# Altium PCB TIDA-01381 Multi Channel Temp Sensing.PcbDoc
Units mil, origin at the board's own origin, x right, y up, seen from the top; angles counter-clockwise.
Board outline 3285 x 2450 mil, 2 copper layers (Top Layer, Bottom Layer), stack 62 mil thick; 83 components, 41 nets, 183 pads, 135 vias.
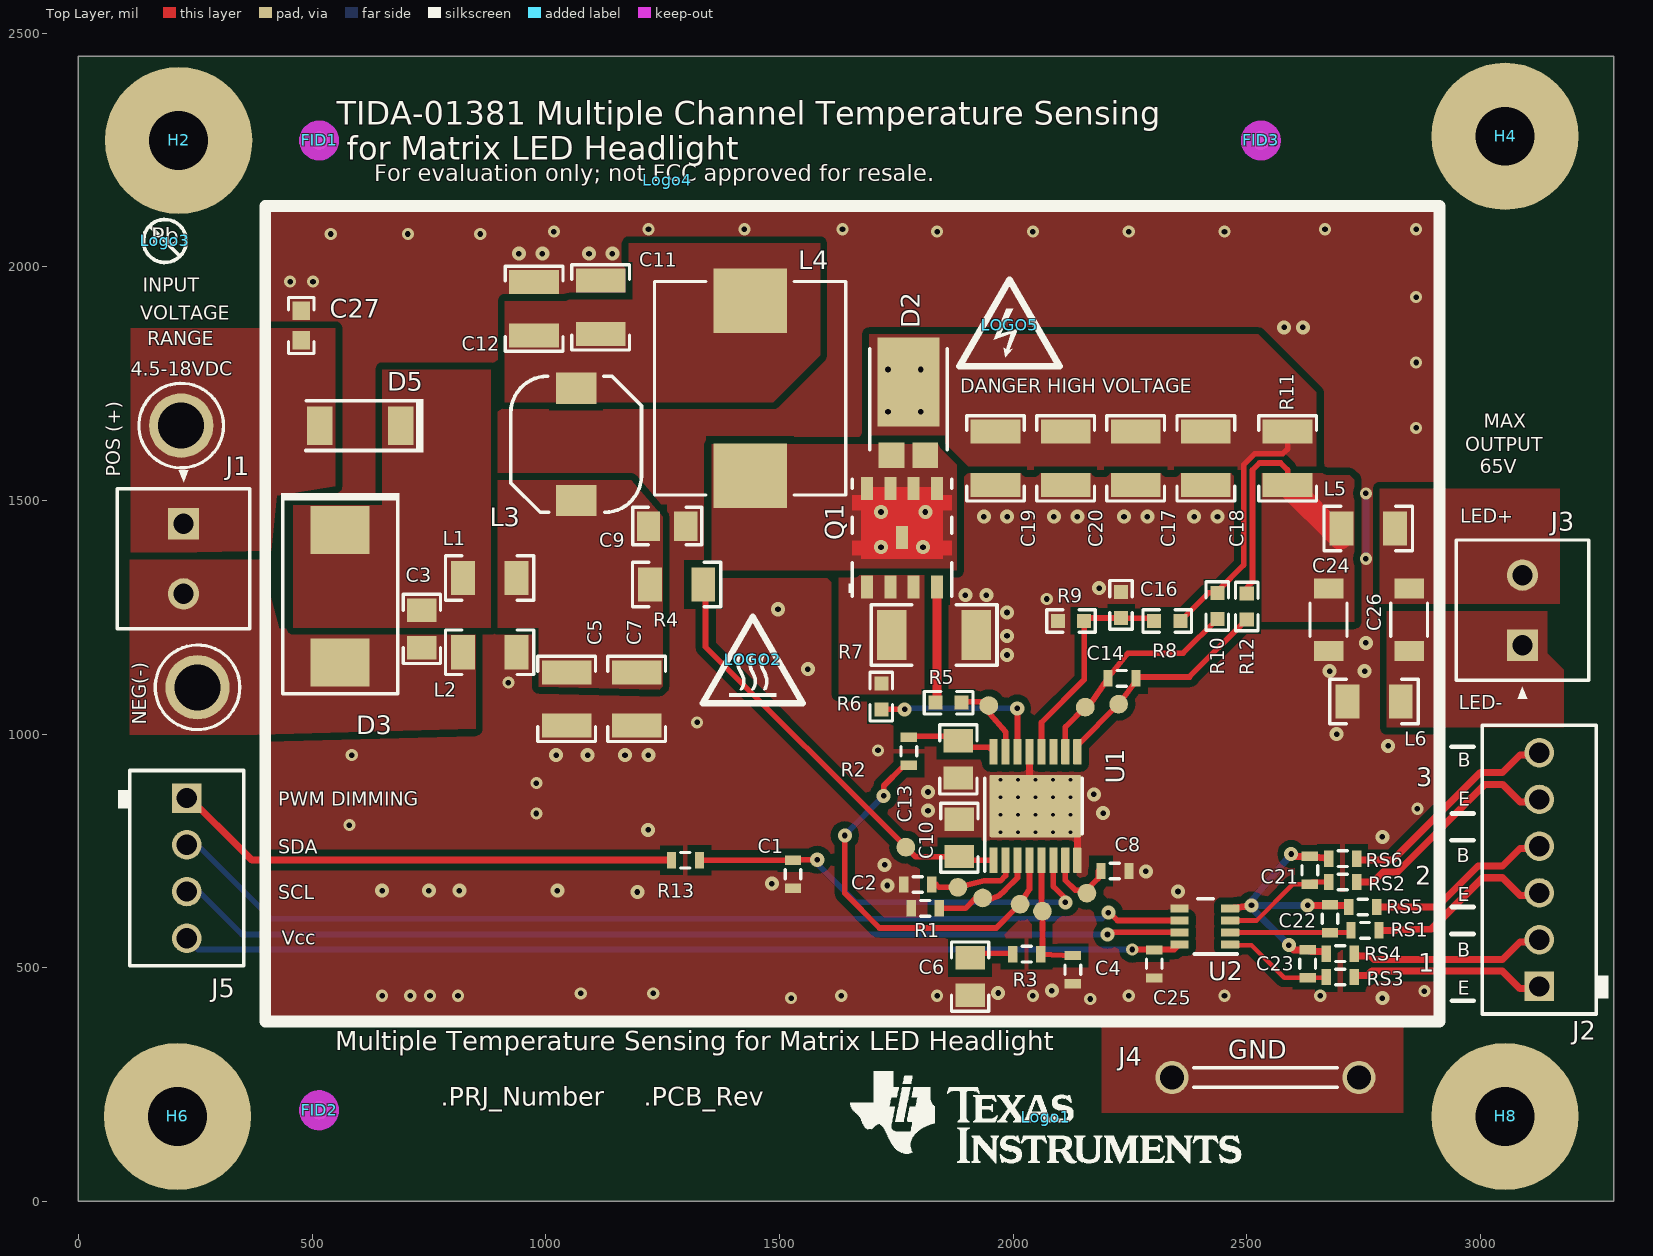
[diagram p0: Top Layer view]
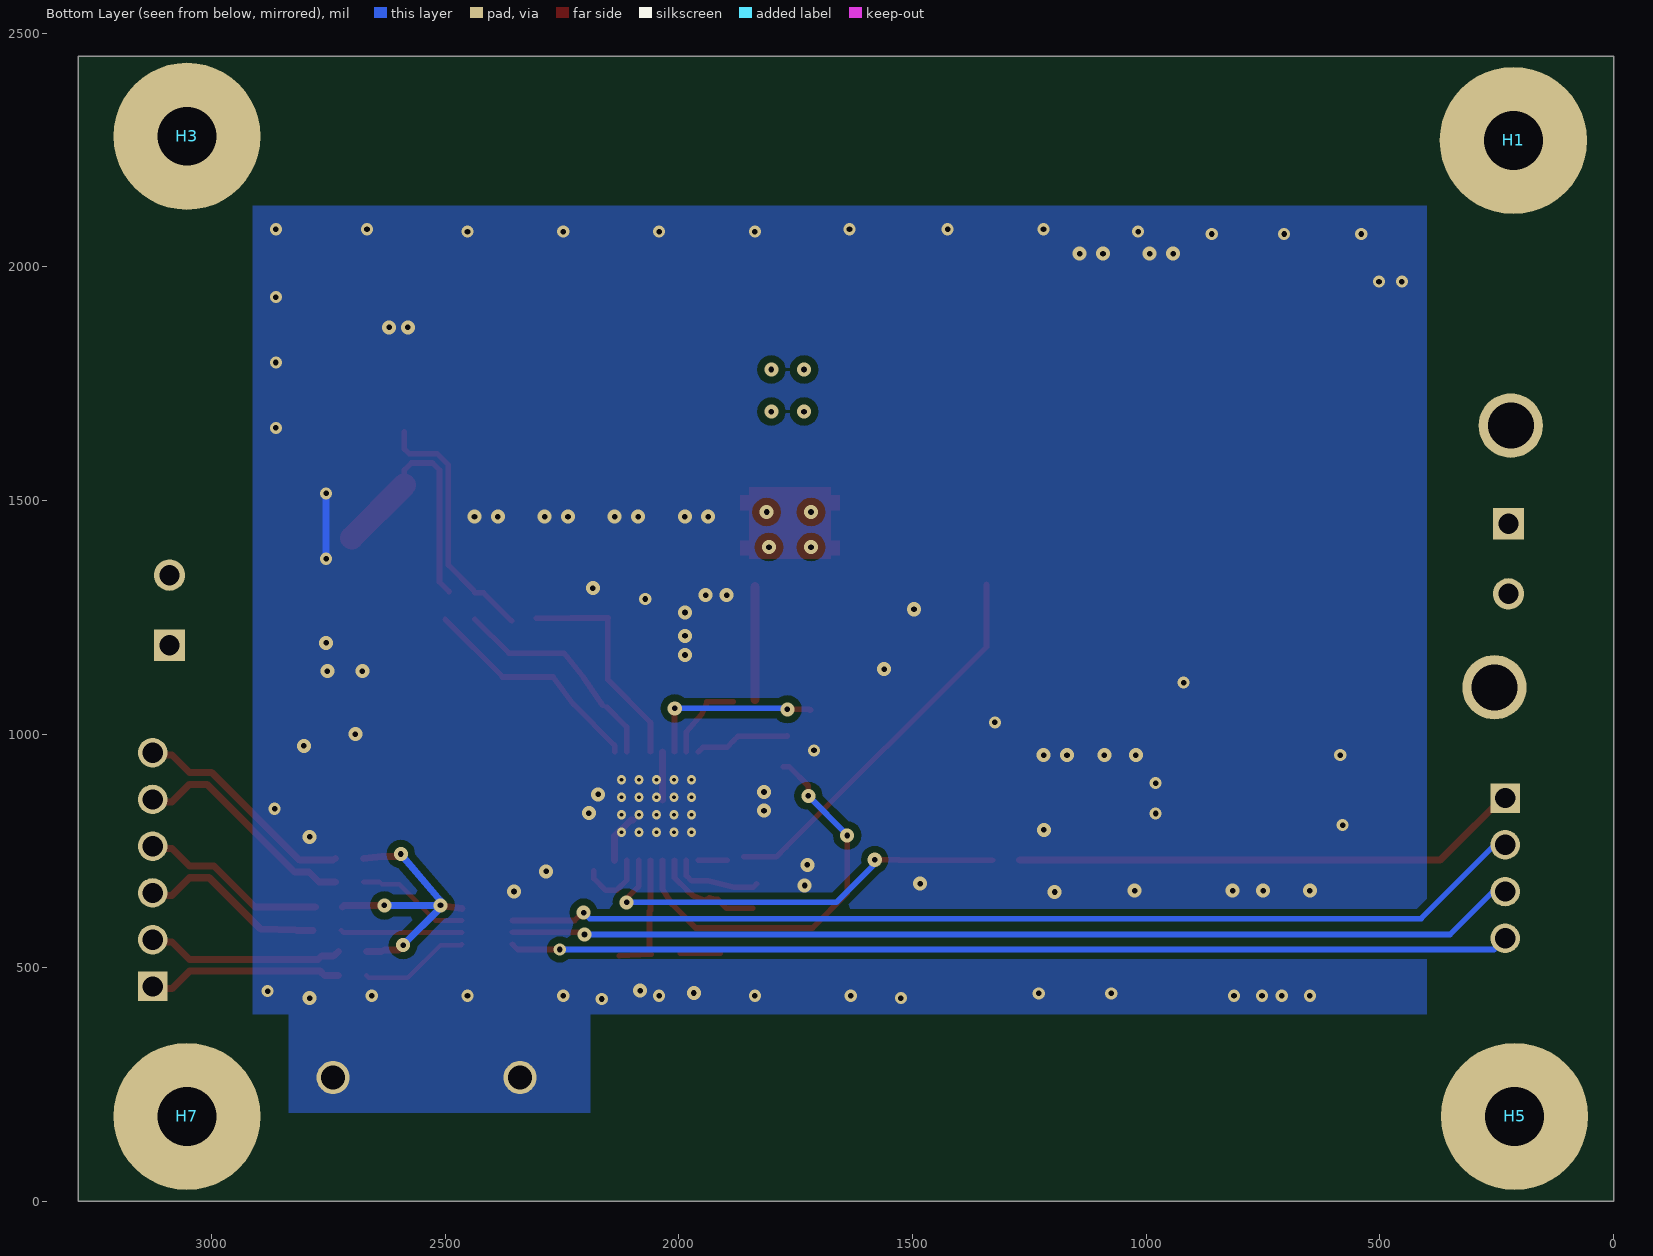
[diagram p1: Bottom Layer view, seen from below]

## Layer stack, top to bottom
Top Solder: solder mask 0.4, Solder Resist, Dk 3.5
Top Layer: signal copper 1.4
Dielectric1: core 59.2, FR-4, Dk 4.8
Bottom Layer: signal copper 1.4
Bottom Solder: solder mask 0.4, Solder Resist, Dk 3.5

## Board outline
0,0 3285,0 3285,2450 0,2450
cut-out: -1242,-1684 -1232,-1684 -1232,-1674 -1242,-1674

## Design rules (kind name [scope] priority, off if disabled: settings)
AcuteAngle [All] p1: minimum=4.50000000000000E+0001 checktracksonly=FALSE
AssemblyTestPointUsage [All] p1 off: valid=2
AssemblyTestpoint [All] p1 off: testpointundercomponent=TRUE minsize=40 maxsize=100 preferedsize=60 minholesize=0 maxholesize=40 preferedholesize=32 testpointgrid=1 usegrid=TRUE gridtolerance=0.01 allowsidetop=TRUE allowsidebottom=TRUE
Clearance Clearance_BoardEdge_Poly [OnCopper and InPoly vs IsKeepOut] p1: gap=25
Clearance Clearance_BoardEdge [OnCopper and Not InComponentClass('Logo') and not InComponentClass('FiducialMark') and not InRegion(1000,500,4000,800) and Not IsKeepout vs IsKeepOut] p2: gap=25
Clearance Clearance_Poly [InPolygon] p3: gap=15
Clearance [All] p4: gap=7
ComponentClearance ComponentClearance_MountingHoles [InComponent('H1') or InComponent('H2')or InComponent('H4') or InComponent('H5') or InComponent('H8')] p1: gap=0 collisioncheckmode=3 verticalgap=0 showdistances=FALSE
ComponentClearance ComponentClearance_Logo [InComponentClass('Logo')] p2: gap=0 collisioncheckmode=3 verticalgap=0 showdistances=FALSE
ComponentClearance ComponentClearance_SmallPassives [HasFootprint('0201*') or HasFootprint('0402*') or HasFootprint('0508') or HasFootprint('0603*') or HasFootprint('0612') or HasFootprint('0805*') or HasFootprint('0815*') or HasFootprint('0830*') or HasFootprint('1206*') or HasFootprint('1210*') or HasFootprint('1808*') or HasFootprint('1812*') or HasFootprint('1825*') or HasFootprint('2010*') or HasFootprint('2220*') or HasFootprint('2225*') or HasFootprint('2512*') or HasFootprint('2728*') or HasFootprint('3518*') vs HasFootprint('0201*') or HasFootprint('0402*') or HasFootprint('0508') or HasFootprint('0603*') or HasFootprint('0612') or HasFootprint('0805*') or HasFootprint('0815*') or HasFootprint('0830*') or HasFootprint('1206*') or HasFootprint('1210*') or HasFootprint('1808*') or HasFootprint('1812*') or HasFootprint('1825*') or HasFootprint('2010*') or HasFootprint('2220*') or HasFootprint('2225*') or HasFootprint('2512*') or HasFootprint('2728*') or HasFootprint('3518*')] p3: gap=10 collisioncheckmode=3 verticalgap=10 showdistances=FALSE
ComponentClearance [All] p4: gap=15 collisioncheckmode=3 verticalgap=30 showdistances=FALSE
DiffPairsRouting [All] p1: maxlimit=100 minlimit=10 mostfreqgap=10 toplayer_minwidth=15 toplayer_maxwidth=15 toplayer_prefwidth=15 bottomlayer_minwidth=15 bottomlayer_maxwidth=15 bottomlayer_prefwidth=15 maxuncoupledlength=1000
FabricationTestPointUsage TestPointUsage [All] p1 off: valid=2 allowmultiple=FALSE
FabricationTestpoint Testpoint [All] p1 off: side=3 testpointundercomponent=TRUE minsize=40 maxsize=100 preferedsize=60 minholesize=0 maxholesize=40 preferedholesize=32 testpointgrid=1 allowsidetop=TRUE allowsidebottom=TRUE usegrid=TRUE gridtolerance=0.01
FanoutControl Fanout_LCC [IsLCC] p1: bgadir=Out bgaviamode=Centered fanoutstyle=Auto fanoutdirection=Alternating viagrid=1 // Fanout_LCC (Default Rule)
FanoutControl Fanout_BGA [IsBGA] p2: bgadir=Out bgaviamode=Centered fanoutstyle=Auto fanoutdirection=Alternating viagrid=1 // Fanout_BGA (Default Rule)
FanoutControl Fanout_Default [All] p4: bgadir=Out bgaviamode=Centered fanoutstyle=Auto fanoutdirection=Alternating viagrid=1 // Fanout_Default (Default Rule)
FanoutControl Fanout_Small [(CompPinCount < 5)] p5: bgadir=Out bgaviamode=Centered fanoutstyle=Auto fanoutdirection=OutThenIn viagrid=1 // Fanout_Small (Default Rule)
HoleSize [All] p1: absolutevalues=TRUE maxlimit=251 minlimit=7.87 maxpercent=80.000 minpercent=20.000
MinimumAnnularRing MinimumAnnularRing_ThermalPadVias [IsVia and InAnyComponent] p1: minimumring=5.5
MinimumAnnularRing [All] p2: minimumring=5.5
MinimumSolderMaskSliver MinimumSolderMaskSliver_Logo [InComponentClass('Logo') vs InComponentClass('Logo')] p1: minsoldermaskwidth=0.7
MinimumSolderMaskSliver [All] p2: minsoldermaskwidth=3.94
PlaneConnect [All] p1: planeconnectstyle=Relief reliefexpansion=10 reliefentries=4 reliefconductorwidth=10 reliefairgap=10
PolygonConnect [All] p1: connectstyle=Direct reliefconductorwidth=10 reliefentries=4 polygonreliefangle="90 Angle" airgapwidth=10
RoomDefinition "TIDA-01381 Multi Channel Temp Sensing_Hardware" [InComponentClass('TIDA-01381 Multi Channel Temp Sensing_Hardware')] p1: confinementstyle=ConfineIn formatcopy=TRUE lockcomponents=FALSE outline -1242,-1684 758,-1684 758,-684 -1242,-684
RoomDefinition "TIDA-01381 Multi Channel Temp Sensing_2" [InComponentClass('TIDA-01381 Multi Channel Temp Sensing_2')] p2: confinementstyle=ConfineIn formatcopy=TRUE lockcomponents=FALSE outline -1242,-1684 758,-1684 758,-684 -1242,-684
RoutingVias ThermalPadVias [IsVia and InAnyComponent] p1: holewidth=7.87 width=26 viastyle="Through Hole" minholewidth=7.87 minwidth=19.68 maxholewidth=15 maxwidth=26
RoutingVias [All] p2: holewidth=16 width=34 viastyle="Through Hole" minholewidth=7.87 minwidth=26 maxholewidth=40 maxwidth=65
SilkToBoardRegionClearance [Not ((IsComment or IsDesignator) And (Hide <> 'False')) and not InRegion(1000,500,4000,800)] p1:
SilkToSilkClearance SilkToSilkClearance_Pb-FreeLogo [(HasFootprint('Pb-Free_Overlay_Medium') OR HasFootprint('Pb-Free_Overlay_Small')) vs (HasFootprint('Pb-Free_Overlay_Medium') OR HasFootprint('Pb-Free_Overlay_Small'))] p1: silktosilkclearance=0
SilkToSilkClearance [All] p2: silktosilkclearance=4
SilkToSolderMaskClearance SilkToSolderMaskClearance_PhxContact [(HasFootprint('PhoenixConact_1727010') OR HasFootprint('Phoenix_1727023'))] p1: minsilkscreentomaskgap=-1 clearancetoexposedcopper=TRUE
SilkToSolderMaskClearance SilkToSolderMaskClearance_Vias [IsVia] p2: minsilkscreentomaskgap=-1 clearancetoexposedcopper=TRUE
SilkToSolderMaskClearance [IsPad] p3: minsilkscreentomaskgap=5 clearancetoexposedcopper=TRUE
SilkToSolderMaskClearance "Silk to Solder Mask Opening" [All] p4: minsilkscreentomaskgap=4 clearancetoexposedcopper=FALSE
SolderMaskExpansion [All] p1: expansion=1.97
Width [All] p1: maxlimit=100 minlimit=7 preferedwidth=12 minimp=50.000000 maximp=50.000000 favimp=50.000000 checkconnectedcopper=TRUE
14 further rules are at their usual default settings.

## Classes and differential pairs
component class "TIDA-01381 Multi Channel Temp Sensing_2": C1 C2 C3 C4 C5 C6 C7 C8 C9 C10 C11 C12 C13 C14 C16 C17 C18 C19 C20 C21 C22 C23 C24 C25 C26 C27 C33 D2 D3 D5 J1 J2 J3 J4 J5 L1 L2 L3 L4 L5 L6 NEG(-) "POS (+)" Q1 R1 R2 R3 R4 R5 R6 R7 R8 R9 R10 R11 R12 R13 R23 R28 RS1 RS2 RS3 RS4 RS5 RS6 U1 U2
component class Logo: Logo1
component class "TIDA-01381 Multi Channel Temp Sensing_Hardware": FID1 FID2 FID3 H1 H2 H3 H4 H5 H6 H7 H8 Logo1 LOGO2 Logo3 Logo4 LOGO5 ZZ1 ZZ2 ZZ3
component class FiducialMark: FID1 FID2 FID3
component class AssemblyNote: ZZ1 ZZ2 ZZ3
component class "Mounting Holes": H2 H4 H6 H8

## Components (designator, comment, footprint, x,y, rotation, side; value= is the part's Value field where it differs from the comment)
C1 "06033C104JAT2A" 0603S 1529,700 r270 top
C2 "06033C104JAT2A" 0603S 1796,678 r180 top
C3 "C2012X7R2A104K125AA" 0805_HV 735,1225 r270 top
C4 "GRM188R71E332KA01D" 0603S 2128,496 r270 top
C5 "C3225X7S2A475K200AE" 1210 1044.68,1075 r270 top
C6 "GRM216R71E333KA01D" 0805_HV 1908,481 r90 top
C7 "C3225X7S2A475K200AE" 1210 1194.68,1075 r270 top
C8 "CGA3E2C0G1H100D080AA" 0603S 2218,707 r0 top
C9 "C2012X7R2A104K125AA" 0805_HV 1260,1445 r0 top
C10 "C2012X7R2A104K125AA" 0805_HV 1885,778 r270 top
C11 "C3225X7S2A475K200AE" 1210 1117.64,1912.91 r90 top
C12 "C3225X7S2A475K200AE" 1210 975,1910 r90 top
C13 "C0805C225K4RACTU" 0805_HV 1882.91,945.91 r270 top
C14 "GRM188R71H104KA93D" 0603S 2233,1119 r0 top
C16 "06031C102JAT2A" 0603_HV 2231,1276.33 r90 top
C17 "C3225X7S2A475K200AE" 1210 2262.36,1590 r90 top
C18 "C3225X7S2A475K200AE" 1210 2412.36,1590 r90 top
C19 "C3225X7S2A475K200AE" 1210 1962.36,1590 r90 top
C20 "C3225X7S2A475K200AE" 1210 2112.36,1590 r90 top
C21 "CGA3E2NP01H101J080AA" 0603S 2635.16,708.27 r90 top
C22 "CGA3E2NP01H101J080AA" 0603S 2678,605 r90 top
C23 "CGA3E2NP01H101J080AA" 0603S 2630.16,508.27 r90 top
C24 "C3216X7R2A104K160AA" 1206_180 2675,1244.69 r270 top
C25 "06033C104JAT2A" 0603S 2302,508 r270 top
C26 "C3216X7R2A104K160AA" 1206_180 2847.36,1244.69 r270 top
C27 "GRT188R61H225KE13D" 0603 477,1874 r90 top
D2 "PDS3100Q-13" PowerDI5 1776.16,1674.87 r90 top
D3 "TPSMD24A" SMC_265 560,1295 r270 top
D5 "PMEG10030ELPX" SOD-128 603,1660 r180 top
FID1 "Fiducial" Fiducial10-20 515,2270 r0 top
FID2 "Fiducial" Fiducial10-20 515,195 r0 top
FID3 "Fiducial" Fiducial10-20 2530,2270 r0 top
H1 "1902C" Keystone_1902C 215,2270 r180 bottom
H2 "NY PMS 440 0025 PH" "NY PMS 440 0025 PH" 214.64,2270 r0 top
H3 "1902C" Keystone_1902C 3053.07,2279.06 r180 bottom
H4 "NY PMS 440 0025 PH" "NY PMS 440 0025 PH" 3052.72,2279.06 r0 top
H5 "1902C" Keystone_1902C 211.85,181.85 r180 bottom
H6 "NY PMS 440 0025 PH" "NY PMS 440 0025 PH" 211.85,181.85 r0 top
H7 "1902C" Keystone_1902C 3053.07,181.85 r180 bottom
H8 "NY PMS 440 0025 PH" "NY PMS 440 0025 PH" 3052.72,181.85 r0 top
J1 "1727010" PhoenixConact_1727010 225,1375 r270 top
J2 "1725698" Phoenix_1725698 3126,710 r90 top
J3 "1727010" PhoenixConact_1727010 3090,1265 r90 top
J4 "D3082-05" Harwin_D3082-05 2540,265 r180 top
J5 "1725672" Phoenix_1725672 232,713 r270 top
L1 "FBMH3216HM221NTV" 1206 880,1334 r0 top
L2 "FBMH3216HM221NTV" 1206 880,1175 r0 top
L3 "CLF7045T-3R3N" CLF7045 1065,1620 r90 top
L4 "IHLP4040DZER220M8A" IHLP-4040DZ 1437.36,1740 r270 top
L5 "BLM31PG601SH1L" 1206 2760,1439.69 r0 top
L6 "BLM31PG601SH1L" 1206 2772.36,1069.69 r0 top
Logo1 "Texas Instruments" TI_Stacked_Overlay_Small 2070,180 r0 top
LOGO2 "CAUTION HOT SURFACE" IEC_HotSurface_Small 1443,1159 r0 top
Logo3 "Pb-Free Symbol" Pb-Free_Overlay_Small 185,2055 r0 top
Logo4 "FCC disclaimer" FCC_disclaimer 1260,2185 r0 top
LOGO5 "DANGER HIGH VOLTAGE" IEC_HighVoltage_Small 1992.36,1875 r0 top
NEG(-) "GND" Keystone1502-2 255,1100 r180 top
"POS (+)" "Suggest using a net name here" Keystone1502-2 220,1660 r0 top
Q1 "STL8N10LF3" PowerFLAT5x6_R 1762.36,1420.32 r90 top
R1 "CRCW060320K0FKEA" 0603S 1812,627 r0 top
R2 "CRCW0603100KFKEA" 0603S 1777,963 r270 top
R3 "CRCW06031K43FKEA" 0603S 2029,529 r0 top
R4 "CRCW120610R0FKEA" 1206 1280,1320 r180 top
R5 "CRCW06030000Z0EA" 0603_HV 1862,1067 r180 top
R6 "CRCW0603100RFKEA" 0603_HV 1718,1080 r90 top
R7 "CSRN2010FK60L0" 2010 1831,1212 r180 top
R8 "CRCW0603487KFKEA" 0603_HV 2330,1242 r0 top
R9 "CRCW060310K0FKEA" 0603_HV 2124,1242 r0 top
R10 "CRCW060310R0FKEA" 0603_HV 2437,1274 r90 top
R11 "MCR25JZHFLR160" 1210 2587.36,1590 r270 top
R12 "CRCW060310R0FKEA" 0603_HV 2500,1273 r90 top
R13 "CRCW0603220RJNEA" 0603S 1299,730 r180 top
RS1 "ERJ-3GEY0R00V" 0603S 2753,580 r180 top
RS2 "ERJ-3GEY0R00V" 0603S 2705.16,683.27 r180 top
RS3 "ERJ-3GEY0R00V" 0603S 2700,480 r180 top
RS4 "ERJ-3GEY0R00V" 0603S 2700,530 r180 top
RS5 "ERJ-3GEY0R00V" 0603S 2748,630 r180 top
RS6 "ERJ-3GEY0R00V" 0603S 2705.16,733.27 r0 top
U1 "TPS92691QPWPRQ1" PWP0016J_N 2047.91,845.91 r90 top
U2 "TMP423AQDCNRQ1" DCN0008A_N 2410.16,588.27 r180 top
ZZ1 "These assemblies are ESD sensitive, ESD precautions shall be observed." AssemblyNote 25,3560 r0 top
ZZ2 "These assemblies must be clean and free from flux and all contaminants. Use of no clean flux is not acceptable." AssemblyNote 25,3455 r0 top
ZZ3 "These assemblies must comply with workmanship standards IPC-A-610 Class 2, unless otherwise specified." AssemblyNote 25,3350 r0 top

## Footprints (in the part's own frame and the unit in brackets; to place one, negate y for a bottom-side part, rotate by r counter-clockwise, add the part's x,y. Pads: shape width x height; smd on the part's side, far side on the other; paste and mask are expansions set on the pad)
0603 [mm] "0603 from SM-752 data"
  rect 1x0.95 smd: 1(-0.8,0) 2(0.8,0)
  silkscreen extent -1.52,-0.69 1.52,0.69, body extent -0.87,-0.47 0.87,0.47, height 1
0603_HV [mil] "Ernesto recommended land pattern.  26 mil between pads."
  rect 30x30 smd: 1(-28,0) 2(28,0)
  silkscreen extent -52,-24 52,24, body extent -34,-19 34,19, height 39
0603S [mil]
  rect 20x35 smd: 1(-30,0) 2(30,0)
  silkscreen extent -10,-17 10,17, body extent -34,-19 34,19, height 39
0805_HV [mil] "0805 with 30mil clearance between pads"
  rect 50x63 smd: 1(-40,0) 2(40,0)
  silkscreen extent -74,-40 74,40, body extent -43,-29 43,29, height 57
1206 [mm] "1206 from SM-752 data"
  rect 1.3x1.85 smd: 1(-1.45,0) 2(1.45,0)
  silkscreen extent -2.4,-1.21 2.4,1.21, body extent -1.7,-0.9 1.7,0.9, height 1.35
1206_180 [mm] "1206_180"
  rect 1.1x1.6 smd: 1(-1.7,0) 2(1.7,0)
  silkscreen extent -0.9,-1 0.9,1, body extent -1.75,-0.95 1.75,0.95, height 1.8
1210 [mm] "1210 from SM-752 data"
  rect 1.3x2.7 smd: 1(-1.45,0) 2(1.45,0)
  silkscreen extent -2.32,-1.57 2.32,1.57, body extent -1.7,-1.35 1.7,1.35, height 1.35
2010 [mm] "Chip Capacitor, Body 5.08x2.54mm, IPC Medium Density"
  rect 1.6x2.7 smd: 1(-2.3,0) 2(2.3,0)
  silkscreen extent -3.42,-1.65 3.42,1.65, body extent -2.73,-1.45 2.73,1.45, height 1.66
AssemblyNote [mil] "Assembly Note"
CLF7045 [mm] "TDK"
  rect 1.7x2.2 smd: 1(-3.05,0) 2(3.05,0)
  silkscreen extent -3.7,-3.55 3.7,3.55, body extent -3.7,-3.55 3.7,3.55, height 4.8
DCN0008A_N [mm] "SOP, 8-Leads, Body 2.9x1.6mm, Pitch 0.65mm, IPC Medium Density"
  rrect22% 1x0.45 smd: 1(-1.375,0.975) 2(-1.375,0.325) 3(-1.375,-0.325) 4(-1.375,-0.975) 5(1.375,-0.975) 6(1.375,-0.325) 7(1.375,0.325) 8(1.375,0.975)
  silkscreen extent -1.75,-1.5 0.58,1.5, body extent -1.41,-1.45 1.41,1.45, height 1.45
FCC_disclaimer [mil]
Fiducial10-20 [mm]
  round 1 smd mask+0.5: 1(0,0)
  Top Layer keep-out circle w1.178: c0,0 r0.5
Harwin_D3082-05 [mm] "Shorting Plug, 10.16mm spacing, TH"
  round 1.8 hole 1.3: 1(-5.08,0) 2(5.08,0)
  silkscreen extent -3.9,-0.53 3.9,0.53, body extent -5.6,-0.52 5.61,0.52, height 6.63
IEC_HighVoltage_Small [mil]
  silkscreen extent -107,-88 107,97
IEC_HotSurface_Small [mil]
  silkscreen extent -107,-93 107,92
IHLP-4040DZ [mm] "Vishay Dale recommended land pattern.  Document 34192 rev 04-Jul-08"
  rect 3.5x4 smd: 1(-4.75,0) 2(4.75,0)
  silkscreen extent -5.8,-5.2 5.8,5.2, body extent -5.75,-5.15 5.75,5.15, height 4
Keystone1502-2 [mm] "Double Turret"
  round 3.5 hole 2.5: 1(0,0)
  silkscreen extent -2.3,-2.3 2.3,2.3, body extent -1.6,-1.6 1.59,1.6, height 5.62
Keystone_1902C [mil] "Hex Standoff, 4-40 threaded, nylon"
  round 1 on Mech4: 0(0,0)
  body extent -145,-126 146,126, height 501
"NY PMS 440 0025 PH" [mm] "4-40 nylon screw and mounting hole"
  round 8 hole 3.2: 1(0,0)
  body extent -3.3,-3.3 3.3,3.3, height 2.69
Pb-Free_Overlay_Small [mil]
  silkscreen extent -46,-46 46,46
Phoenix_1725672 [mm] "Terminal Block, 4x1, 2.54 mm, TH"
  rect 1.6x1.6 hole 1.1: 1(-3.81,0)
  round 1.6 hole 1.1: 2(-1.27,0) 3(1.27,0) 4(3.81,0)
  silkscreen extent -5.31,-3.75 5.31,3.1, body extent -5.31,-3.1 5.31,3.1, height 9.01
Phoenix_1725698 [mm] "Terminal Block, 6x1, 2.54mm, TH"
  rect 1.6x1.6 hole 1.1: 1(-6.35,0)
  round 1.6 hole 1.1: 2(-3.81,0) 3(-1.27,0) 4(1.27,0) 5(3.81,0) 6(6.35,0)
  silkscreen extent -7.85,-3.75 7.85,3.1, body extent -7.85,-3.1 7.85,3.1, height 8.51
PhoenixConact_1727010 [mm]
  rect 1.7x1.7 hole 1.1: 1(-1.905,0)
  round 1.7 hole 1.1: 2(1.905,0)
  silkscreen extent -4.8,-3.6 3.81,3.6, body extent -3.81,-3.6 3.81,3.7, height 8.52
PowerDI5 [mm] "Diodes Inc recommended land pattern, ap02001.pdf rev 60"
  rect 1.4x1.39 smd: 1(-1.991,0.92) 2(-1.991,-0.92)
  rect 4.86x3.36 smd: 3(1.991,0)
  silkscreen extent -1.7,-2.1 3.8,2.1, body extent -2.27,-2.03 4.33,2.03, height 1.17
PowerFLAT5x6_R [mm] "SMD, 8-Leads, Body 6.15x5.2mm, Pitch 1.27mm"
  rect 1.25x0.65 smd: 1(-2.675,1.905) 2(-2.675,0.635) 3(-2.675,-0.635) 4(-2.675,-1.905) 5(2.675,-1.905) 6(2.675,-0.635) 7(2.675,0.635) 8(2.675,1.905) 9(0,0)
  Top Layer region: -0.96,2.7 -0.96,2.225 -1.15,2.225 -1.15,-2.225 -0.96,-2.225 -0.96,-2.7 -0.16,-2.7 -0.16,-2.225 1.49,-2.225 1.49,-2.7 2.29,-2.7 2.29,-2.225 2.75,-2.225 2.75,2.225 2.29,2.225 2.29,2.7 1.49,2.7 1.49,2.225 -0.16,2.225 -0.16,2.7
  silkscreen extent -3.17,-2.7 3.17,2.9, body extent -3.17,-2.7 3.17,2.7, height 1.01
PWP0016J_N [mm] "TSOP, 16-Leads, Body 5x4.4mm, Pitch 0.65mm, Exposed Pad, IPC Medium Density"
  rrect22% 1.4x0.45 smd: 1(-2.95,2.275) 2(-2.95,1.625) 3(-2.95,0.975) 4(-2.95,0.325) 5(-2.95,-0.325) 6(-2.95,-0.975) 7(-2.95,-1.625) 8(-2.95,-2.275) 9(2.95,-2.275) 10(2.95,-1.625) 11(2.95,-0.975) 12(2.95,-0.325) 13(2.95,0.325) 14(2.95,0.975) 15(2.95,1.625) 16(2.95,2.275)
  rrect6% 3.4x5 smd paste-1.7 mask-1.7: 17(0,0)
  rrect4% 2.46x3.55 on Top Paste: 17(0,0)
  rrect4% 2.46x3.55 on Top Solder: 17(0,0)
  silkscreen extent -3.55,-2.55 1.5,2.75, body extent -3.21,-2.5 3.21,2.5, height 1
SMC_265 [mm] "SMD, 2-Leads, Body 7.15x6.25mm"
  rect 2.6x3.2 smd: 1(-3.6,0) 2(3.6,0)
  silkscreen extent -5.6,-3.22 5.3,3.23, body extent -4.07,-3.13 4.07,3.13, height 2.65
SOD-128 [mm] "SMD, 2-Leads, Body 4x2.7mm, Height 1.1mm"
  rect 1.4x2.1 smd paste-0.1: 1(-2.2,0) 2(2.2,0)
  silkscreen extent -3.45,-1.45 2.95,1.45, body extent -2.5,-1.35 2.5,1.35, height 1.1
TI_Stacked_Overlay_Small [mil]
  silkscreen extent -418,-98 418,98

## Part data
C1 C2 C25: "CAP, CERM, 0.1 µF, 25 V, +/- 5%, X7R, 0603"
C3 C9 C10: "CAP, CERM, 0.1 µF, 100 V, +/- 10%, X7R, 0805"
C4: "CAP, CERM, 3300 pF, 25 V, +/- 10%, X7R, 0603"
C5 C7 C11 C12 C17 C18 C19 C20: "CAP, CERM, 4.7 µF, 100 V, +/- 10%, X7S, 1210"
C6: "CAP, CERM, 0.033 µF, 25 V, +/- 10%, X7R, 0805"
C8: "CAP, CERM, 10 pF, 50 V, +/- 5%, C0G/NP0, AEC-Q200 Grade 1, 0603"
C13: "CAP, CERM, 2.2 µF, 16 V, +/- 10%, X7R, 0805"
C14: "CAP, CERM, 0.1 µF, 50 V, +/- 10%, X7R, 0603"
C16: "CAP, CERM, 1000 pF, 100 V, +/- 5%, X7R, 0603"
C21 C22 C23: "CAP, CERM, 100 pF, 50 V, +/- 5%, C0G/NP0, AEC-Q200 Grade 0, 0603"
C24 C26: "CAP, CERM, 0.1 µF, 100 V, +/- 10%, X7R, 1206"
C27: "CAP, CERM, 2.2 µF, 50 V, +/- 10%, X5R, AEC-Q200 Grade 3, 0603"
D2: "Diode, Schottky, 100 V, 3 A, AEC-Q101, PowerDI5"
D3: library part TPSMD26A, "Diode, TVS, Uni, 24 V, 38.9 Vc, AEC-Q101, SMC"
D5: "Diode, Schottky, 100 V, 3 A, AEC-Q101, SOD-128"
FID1 FID2 FID3: "Fiducial mark.  There is nothing to buy or mount."
H1 H3 H5 H7: "Standoff, Hex, 0.5\"L #4-40 Nylon"
H2 H4 H6 H8: "Machine Screw, Round, #4-40 x 1/4, Nylon, Philips panhead"
J1 J3: "Conn Term Block, 2POS, 3.81mm, TH"
J2: "Terminal Block, 6x1, 2.54mm, TH"
J4: "1mm Uninsulated Shorting Plug, 10.16mm spacing, TH"
J5: "Terminal Block, 4x1, 2.54 mm, Green, TH"
L1 L2: "Ferrite Bead, 220 ohm @ 100 MHz, 4 A, 1206"
L3: "Inductor, Shielded, Ferrite, 3.3 µH, 5 A, 0.0213 ohm, SMD"
L4: "Inductor, Shielded Drum Core, Powdered Iron, 22 µH, 4.1 A, 0.0705 ohm, AEC-Q200 Grade 0, SMD"
L5 L6: "Ferrite Bead, 600 ohm @ 100 MHz, 1.5 A, 1206"
Logo1: library part TI_Logo, "Texas Instrument Corporate Signature"
LOGO2: library part IEC_HotSurface, "IEC 61010-1 Hot Surface Warning"
Logo3: library part Pb-Free
Logo4: library part FCC_disclaimer, "FCC_disclaimer"
LOGO5: library part IEC_HighVoltage, "IEC 61010-1 High Voltage Warning"
NEG(-) "POS (+)": library part 1502-2, "Terminal, Turret, TH, Double"
Q1: "MOSFET, N-CH, 100 V, 20 A, AEC-Q101, 8-PowerVDFN"
R1: "RES, 20.0 k, 1%, 0.1 W, 0603"
R2: "RES, 100 k, 1%, 0.1 W, 0603"
R3: "RES, 1.43 k, 1%, 0.1 W, 0603"
R4: "RES, 10.0, 1%, 0.25 W, 1206"
R5 RS1 RS2 RS3 RS4 RS5 RS6: "RES, 0, 5%, 0.1 W, 0603"
R6: "RES, 100, 1%, 0.1 W, 0603"
R7: "RES, 0.06, 1%, 1 W, 2010"
R8: "RES, 487 k, 1%, 0.1 W, 0603"
R9: "RES, 10.0 k, 1%, 0.1 W, 0603"
R10 R12: "RES, 10.0, 1%, 0.1 W, 0603"
R11: "RES, 0.16, 1%, 0.5 W, 1210"
R13: "RES, 220, 5%, 0.1 W, 0603"
U1: "Multi-Topology LED Driver with Rail-to-Rail Current Sense Amplifier, PWP0016J"
U2: library part TMP423BIDCNR, "+/- 1 C Remote and Local TEMPERATURE SENSOR, DCN0008A (SOT-8)"
ZZ1 ZZ2 ZZ3: library part AssemblyNote

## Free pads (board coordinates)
  round 40 smd: 1(1770.5,757.91) 1(1882,672) 1(1935,649.26) 1(1948,1061) 1(2015,636) 1(2062.91,620.91) 1(2154.5,1057.61) 1(2158,659.63) 1(2225.95,1063.96)

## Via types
v1: diameter 30, hole 12, Top Layer to Bottom Layer, tented both sides, 70 vias
v2: diameter 26, hole 12, Top Layer to Bottom Layer, tented both sides, 45 vias
v3: diameter 19.68, hole 7.87, Top Layer to Bottom Layer, tented both sides, 14 vias
v4: diameter 19.68, hole 7.87, Top Layer to Bottom Layer, 6 vias

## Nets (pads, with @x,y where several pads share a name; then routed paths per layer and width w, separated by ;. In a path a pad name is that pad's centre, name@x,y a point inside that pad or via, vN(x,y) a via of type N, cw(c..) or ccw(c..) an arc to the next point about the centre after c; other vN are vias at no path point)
DXN1: J2.2 RS4.1 | length 404.1
  Top Layer w15: RS4.1@2728.64,535 2738.64,525 2765,525 2772.5,517.5 3047.5,517.5 3085,555 J2.2@3110,555
DXN2: J2.4 RS5.1 | length 393.8
  Top Layer w15: RS5.1 2835,630 2907.14,630 2994.64,717.5 3047.5,717.5 3085,755 J2.4@3120,755
DXN3: J2.6 RS6.2 | length 473.2
  Top Layer w15: RS6.2@2740,730 2775,730 2812.14,730 2999.64,917.5 3047.5,917.5 3085,955 J2.6@3120,955
DXP1: J2.1 RS3.1 | length 410.9
  Top Layer w15: RS3.1@2728.48,483.27 2758.27,483.27 2767.5,492.5 3047.5,492.5 3085,455 J2.1@3120,455
DXP2: J2.3 RS1.1 | length 432.7
  Top Layer w15: 2817.84,580 RS1.1 2895.77,583.27 3005,692.5 3047.5,692.5 3085,655 J2.3@3120,655
DXP3: J2.5 RS2.1 | length 487
  Top Layer w15: RS2.1 2770.16,683.27 2791.89,705 2822.5,705 3010,892.5 3047.5,892.5 3085,855 J2.5@3120,855
GND: C1.2 C2.2 C4.2 C5.2 C6.1 C7.2 C8.2 C9.2 C10.1 C11.2 C12.2 C13.2 C16.2 C17.1 C18.1 C19.1 C20.1 C24.2 C25.2 C27.2 J4.1 J4.2 L2.2 L6.1 R1.1 R7.1 R9.1 U1.8 U1.13 U1.17@2047.91,845.91 U2.5 | length 348.8
  Top Layer w15: U1.17@2035.11,858.7 U1.13 ; U1.17@2097.91,815.91 2102.91,815.91 2137.47,781.34 U1.8
  Bottom Layer w15: v2(2755,1375) v2(2755,1515)
  other v1: 2790,435 1968,446 2083,451 1196,662 2353,663 650,665 750,665 815,665 1025,665 1731,676 1484,680 2284,706 1725,720 2790,780 1219,795 2192.91,830.91 1817.91,835.91 2172.91,870.91 1817.91,875.91 1022.32,955 1089.68,955 1169.68,955 1219.68,955 2802.36,974.69 2692.36,999.69 2677.36,1134.69 2752.36,1134.69 1561,1139 1987,1169 2755,1195 1987,1210 1987,1260 1497,1267 1898,1297 1943,1297 2184,1312 1937.36,1465 1987.36,1465 2087.36,1465 2137.36,1465 2237.36,1465 2287.36,1465 2387.36,1465 2437.36,1465 2580,1870 2620,1870 942.64,2027.91 992.64,2027.91 1092.64,2027.91 1142.64,2027.91
  other v2: 2165,433 1525,435 650,440 710,440 752.36,440 812.36,440 1632.36,440 1837.36,440 2042.36,440 2247.36,440 2452.36,440 2657.36,440 1075,445 1230,445 2880,450 580,805 980,830 2865,840 980,895 585,955 1711,965 1324,1025 920,1110 2072,1289 2862.36,1655 2862.36,1795 2862.36,1935 453,1968 502,1968 540,2070 705,2070 860,2070 1017.36,2075 1837.36,2075 2042.36,2075 2247.36,2075 2452.36,2075 1220,2080 1425,2080 1635,2080 2667.36,2080 2862.36,2080
  other v3: 1973.1,789.8 2010.5,789.8 2047.91,789.8 2085.31,789.8 2122.71,789.8 1973.1,827.2 2122.71,827.2 1973.1,864.61 2122.71,864.61 1973.1,902.01 2010.5,902.01 2047.91,902.01 2085.31,902.01 2122.71,902.01
  other v4: 2010.5,827.2 2047.91,827.2 2085.31,827.2 2010.5,864.61 2047.91,864.61 2085.31,864.61
IADJ: C1.1 R13.1 U1.6 | length 926.8
  Top Layer w12: R13.1 C1.1 1530,731 v1(1581,731) ; U1.6 2086.29,673.71 2112,648 v1(2112,640)
  Bottom Layer w12: v1(1581,731) 1581,722 1663,640 v1(2112,640)
IMON: C8.1 pad.1@2158,659.63 U1.7 | length 148.5
  Top Layer w12: U1.7 2111.88,686.93 2133.18,665.63 2157,665.63 2182,690.63 C8.1@2182,707
NetC3_1: C3.1 D3.1 D5.1 L1.1
NetC3_2: C3.2 D3.2 J1.2 L2.1 NEG(-).1
NetC4_1: C4.1 pad.1@2062.91,620.91 R3.2 U1.5 | length 258.8
  Top Layer w12: R3.2 C4.1 ; U1.5 2060.7,623.11 2062.91,620.91 R3.2@2062.91,540.91
NetC5_1: C5.1 C7.1 C9.1 L1.2 L3.1 R4.2
NetC6_2: C6.2 R3.1 | length 85.6
  Top Layer w12: C6.2@1911.98,531 R3.1@1997.53,531
NetC10_2: C10.2 pad.1@1770.5,757.91 R4.1 U1.1 | length 900.7
  Top Layer w12: R4.1@1341.91,1320 1341.91,1186.5 1770.5,757.91 1791.1,737.32 C10.2@1861.49,737.32 ; C10.2@1896.76,729.76 U1.1
NetC11_1: C11.1 C12.1 L3.2 L4.1
NetC14_1: C14.1 pad.1@2154.5,1057.61 R10.1 U1.10 | length 473.8
  Top Layer w12: U1.10 2111.88,1014.98 pad.1@2154.5,1057.61 ; pad.1@2163.33,1061.44 C14.1 2245,1173 2364,1173 R10.1
NetC14_2: C14.2 pad.1@2225.95,1063.96 R12.1 U1.9 | length 494.7
  Top Layer w12: U1.9 2137.47,975.48 2225.95,1063.96 2268.78,1122 2378.09,1122 ; 2376,1122 R12.1
NetC16_1: C16.1 R8.1 R9.2 U1.12 | length 466.8
  Top Layer w12: U1.12 2060.7,1024.7 2152.05,1116.05 R9.2 ; R9.2@2151,1248.33 C16.1 ; C16.1@2236,1248 R8.1@2305,1248
NetC17_2: C17.2 C18.2 C19.2 C20.2 D2.3 R8.2 R10.2 R11.1 | length 538.7
  Top Layer w12: R8.2 2418,1302 R10.2 ; R10.2@2440,1308.43 2493.36,1361.79 2493.36,1576 2517.36,1600 2577.36,1600 2587.36,1610 R11.1
  other v1: 1732.36,1690 1802.36,1690 1732.36,1780 1802.36,1780
NetC21_1: C21.1 RS2.2 U2.3 | length 244.9
  Top Layer w10: U2.3 2521.06,601.06 2598.27,678.27 C21.1 2640.16,683.27 RS2.2
NetC21_2: C21.2 C22.2 C23.2 RS4.2 RS5.2 RS6.1 U2.4 | length 664.3
  Top Layer w15: U2.4 v1(2510.16,633.27) ; v1(2590.16,548.27) 2600.16,538.27 C23.2 ; v1(2595.16,743.27) 2600.16,738.27 C21.2 RS6.1 ; v1@2635.16,633.27 2716.68,633.27 RS5.2@2719.95,630 ; C23.2@2636.89,535 RS4.2@2668.64,535
  Bottom Layer w15: v1@2510.16,643.27 v1(2595.16,743.27) ; v1(2590.16,548.27) 2510.16,628.27 v1(2510.16,633.27) 2515.16,638.27 2520.16,633.27 v1(2630.16,633.27)
NetC22_1: C22.1 RS1.2 U2.2 | length 260.8
  Top Layer w10: U2.2 2464.5,575.27 2718.27,575.27 RS1.2
NetC23_1: C23.1 RS3.2 U2.1 | length 235.9
  Top Layer w10: U2.1 2465.91,548.27 2510.16,548.27 2580.16,478.27 C23.1 2663.48,478.27 RS3.2@2668.48,483.27
NetC24_1: C24.1 L5.1 R11.2 R12.2 | length 547.2
  Top Layer w12: R12.2@2492,1305 2512.36,1325.36 2512.36,1565 2527.36,1580 2572.36,1580 2587.36,1565 R11.2
  Top Layer w50: R11.2 L5.1@2700,1420.28
NetC26_1: C26.1 J3.2 L5.2
NetC26_2: C26.2 J3.1 L6.2
NetC27_1: "POS (+).1" C27.1 D5.2 J1.1
NetD2_1: D2.1 D2.2 L4.2 Q1.5 Q1.6 Q1.7 Q1.8 Q1.9
  other v1: 1717.36,1400 1807.36,1400 1717.36,1475 1812.36,1475
NetJ5_1: J5.1 R13.2 | length 1113.7
  Top Layer w15: J5.1@220,881.5 371.5,730 R13.2@1270.95,730
NetQ1_1: Q1.1 Q1.2 Q1.3 R6.2 R7.2
NetQ1_4: Q1.4 R5.2 | length 246.9
  Top Layer w12: R5.2@1837.36,1074.64 R5.2@1840,1072 ; Q1.4 Q1.4@1839.36,1313
  Top Layer w20: R5.2@1837.36,1074.64 Q1.4
NetR5_1: pad.1@1948,1061 R5.1 U1.15 | length 177.9
  Top Layer w12: R5.1@1883.67,1069 1940.11,1069 1942,1061 1951.39,1042.27 1983.93,1004.24 U1.15
NetR6_1: R6.1 U1.14 | length 383.4
  Top Layer w12: R6.1 1719,1051 1721,1053 v1(1768,1053) ; v1@2007.91,1050.91 2009.52,1050.91 U1.14
  Bottom Layer w12: v1(1768,1053) 1769.84,1054.84 v1(2008.92,1054.84)
PWM: pad.1@2015,636 R2.2 U1.4 | length 861.4
  Top Layer w12: v1(1640,783) 1640,659.28 1714.28,585 1964,585 2015,636 2035.11,668.11 U1.4 ; v1(1723.23,867.83) 1723.23,889.23 1763.65,929.65 R2.2@1777,929.65
  Bottom Layer w12: v1(1640,783) 1640,784.6 v1(1723.23,867.83)
SCL: J5.3 U2.7 | length 2175.4
  Top Layer w12: v1(2202,571) 2205.06,571 2209.53,575.47 U2.7
  Bottom Layer w12: J5.3@224.5,672.5 248.5,672.5 350,571 v1(2202,571)
SDA: J5.2 U2.6 | length 2218.4
  Top Layer w12: v1(2204,618) 2206.6,618 2223.54,601.06 U2.6
  Bottom Layer w12: J5.2@220,774 243,774 412,605 2191,605 v1(2204,618)
SHUTDOWN: C2.1 pad.1@1882,672 U1.2 | length 192.1
  Top Layer w12: C2.1@1834,679.5 1841.5,672 1882,672 1937.91,685.91 1972.91,685.91 1983.93,696.93 U1.2
SYNC: pad.1@1935,649.26 R1.2 U1.3 | length 231.3
  Top Layer w12: R1.2 1898,627 1916.91,645.91 1935,649.26 1945.66,644.56 1969.78,653.91 1982.91,665.91 2009.52,692.52 U1.3
VCC: C13.1 R2.1 U1.16 | length 204.5
  Top Layer w12: R2.1@1767.94,996 1768.94,995 1822,995 1873.81,995 C13.1 1897.31,971.5 1948.89,971.5 U1.16
VDD: C25.1 J5.4 U2.8 | length 2151.4
  Top Layer w12: v2(2255,539) 2345.14,539 U2.8
  Bottom Layer w12: J5.4@222,570 229,563 J5.4 256,539 v2(2255,539)
pads on no net: FID1.1 FID2.1 FID3.1 H1.0 H2.1 H3.0 H4.1 H5.0 H6.1 H7.0 H8.1 U1.11 U1.17@2047.91,845.91

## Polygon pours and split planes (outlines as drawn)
NetC26_2 on Top Layer "Top Layer-No Net 11" (solid, remove dead copper, pour order 21): 3178.29,1014.06 3178.29,1137.48 3143.29,1172.48 3143.29,1262.48 2800,1262.48 2800,1014.05
NetC26_1 on Top Layer "Top Layer-No Net 10" (solid, remove dead copper, pour order 19): 3169.51,1525 2785,1525 2785,1278.46 3103.26,1278.46 3169.51,1278.46 3169.51,1331.46 3169.51,1373.46
NetC24_1 on Top Layer "Top Layer-No Net" (solid, remove dead copper, pour order 15): 2730,1558 2730,1240 2532.36,1240 2532.36,1290 2532.36,1558
NetC17_2 on Top Layer "Top Layer-No Net 1" (solid, remove dead copper, pour order 23): 2649.09,1565 2649.09,1730.92 2525,1855 1902.36,1855 1692.36,1855 1692.36,1635 1842.36,1635 1912.36,1565
NetC11_1 on Top Layer "Top Layer-No Net 3" (solid, remove dead copper, pour order 24): 912.36,1710 912.36,1940 1177.36,1940 1177.36,2050 1587.36,2050 1587.36,1810 1487.36,1710 947.36,1710
NetD2_1 on Top Layer "Top Layer-No Net 4" (solid, remove dead copper, pour order 25): 1355,1350 1880,1350 1880,1620 1355,1620
NetQ1_1 on Top Layer "Top Layer-No Net 5" (solid, remove dead copper, pour order 26): 1627.36,1345 1809.86,1345 1809.86,1085 1627.36,1085
NetC27_1 on Top Layer "Top Layer-No Net 2" (solid, remove dead copper, pour order 18): 111.91,1758.09 111.91,1868 550,1868 550,1758.09 550,1530 425,1510 412.5,1392.5 111.91,1385
NetC3_2 on Top Layer "Top Layer-No Net 8" (solid, remove dead copper, pour order 17): 850,1225.52 430,1225.52 390,1373.24 109.41,1373.24 109.41,998.24 383.24,998.24 850,1011 850,1050.01
NetC5_1 on Top Layer "Top Layer-No Net 9" (solid, remove dead copper, pour order 20): 1250,1095 985,1101.39 985,1227.36 890,1227.36 890,1543.43 1182.83,1543.43 1250,1465
GND on Top Layer "GND_L01_P028" (solid, remove dead copper, pour order 28): 400,2126.52 400,395 2906.8,395 2906.8,2131.52 2901.8,2126.52
NetC3_1 on Top Layer "NETC3_1_L01_P016" (solid, remove dead copper, pour order 16): 460,1490 650,1490 650,1780 882.5,1780 882.5,1227.93 460,1227.93
GND on Top Layer "GND_L01_P030" (solid, remove dead copper, pour order 30): 2190,410 2835,410 2835,190 2190,190
GND on Bottom Layer "GND_L02_P027" (solid, remove dead copper, pour order 27): 400,2130 400,400 2912.36,400 2912.36,2130
GND on Bottom Layer "GND_L02_P032" (solid, remove dead copper, pour order 32): 2190,430 2195,425 2835,425 2835,190 2190,190

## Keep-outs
Keep-Out Layer:
  text ".Layer_Name" at 27,-1008.49 h60

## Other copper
Top Layer:
  text ".Layer_Name" at 27,-1008.49 h60
Bottom Layer:
  text ".Layer_Name" at 27,-1008.49 h60

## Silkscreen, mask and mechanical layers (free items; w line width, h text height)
Top Overlay:
  lines w10: 2938,572 2985,572 ; 2938,773 2985,773 ; 2938,973 2985,973 ; 2939,429 2986,429 ; 2939,630 2986,630 ; 2939,830 2986,830
  lines w25: 400,385 2912.36,385 2912.36,2130 400,2130 400,385
  text "TIDA-01381 Multiple Channel Temperature Sensing /  for Matrix LED Headlight" at 553,2229 h50
  text "INPUT" at 137.29,1946.39 h30
  text "VOLTAGE" at 132.29,1886.39 h30
  text "RANGE" at 147.29,1831.39 h30
  text "4.5-18VDC" at 112.29,1766.39 h30
  text "MAX" at 3007.36,1655 h30
  text "OUTPUT" at 2967.36,1605 h30
  text "65V" at 2999,1558 h30
  text "LED+" at 2957,1452 h30
  text "LED-" at 2954,1053 h30
  text "B" at 2952,930 h30
  text "3" at 2863,888 h40
  text "PWM DIMMING" at 428,847 h30
  text "E" at 2953,847 h30
  text "SDA" at 428,744 h30
  text "B" at 2949,726 h30
  text "2" at 2860,677 h40
  text "SCL" at 428,647 h30
  text "E" at 2951,642 h30
  text "Vcc" at 435,549 h30
  text "B" at 2950,523 h30
  text "1" at 2867,491 h40
  text "E" at 2952,442 h30
  text "Multiple Temperature Sensing for Matrix LED Headlight" at 550,310 h70
  text "GND" at 2460,305 h40
  text ".PRJ_Number" at 775,205 h40
  text ".PCB_Rev" at 1210,205 h40
  text ".Layer_Name" at 27,-1008.49 h60
Bottom Overlay:
  text ".Layer_Name" at 27,-1008.49 h60
Top Paste:
  text ".Layer_Name" at 27,-1008.49 h60
Bottom Paste:
  text ".Layer_Name" at 27,-1008.49 h60
Top Solder:
  text ".Layer_Name" at 27,-1008.49 h60
  text ".Layer_Name" at 27,-1008.49 h60
Bottom Solder:
  region: 2112.2,797.04 2112.2,892.04 1972.2,892.04 1972.2,797.04
  text ".Layer_Name" at 27,-1008.49 h60
Drill Guide:
  text ".Layer_Name" at 27,-1008.49 h60
M1 Board Outline:
  the board outline again, w10
  text ".Layer_Name" at 27,-1008.49 h60
M2 Board Dimensions:
  text ".Layer_Name" at 27,-1008.49 h60
M3 3D STEP Top:
  text ".Layer_Name" at 27,-1008.49 h60
M4 3D STEP Bottom:
  text ".Layer_Name" at 27,-1008.49 h60
M5 Assembly Top:
  lines w10: -842,-1080.17 5758,-1080.17 ; -842,-876.83 5760,-876.83 ; -842,-673.5 -842,-1283.5 3163,-1283.5 5760,-1283.5 5760,-673.5 -841.5,-673.5 -841.5,-1283.5 734,-1283.5 ; 1623,-1283.5 1623,-673.5 ; 2890,-876.83 2890,-673.5 ; 3730,-876.83 3730,-673.5 ; 4352,-1290 4352,-1087.17
  text "COMPONENTS MARKED 'DNP' SHOULD NOT BE POPULATED." at 603.5,-468.5 h60
  text "ASSEMBLY VARIANT:" at 603,-584 h60
  text ".VariantName" at 1639,-584 h60
  text "PCB VIEWED FROM TOP SIDE" at -778.5,-805.67 h60
  text "BOARD #:" at 1698,-805.67 h60
  text ".PRJ_Number" at 2243.5,-805.67 h60
  text "REV:" at 3088,-805.67 h60
  text ".PCB_Rev" at 3379.5,-805.67 h60
  text "SVN REV:" at 3926,-805.67 h60
  text ".VersionControl_RevNumber" at 4432,-805.67 h60
  text "TID #:" at 1698,-1009 h60
  text ".TID" at 2243.5,-1009 h60
  text "PLOT NAME =" at -778.5,-1214.34 h60
  text "GENERATED    :" at 1700,-1214.34 h60
  text ".Print_Date" at 2569.5,-1214.34 h60
  text ".Print_Time" at 3298.5,-1214.34 h60
  text "TEXAS INSTRUMENTS" at 4563,-1214.34 h60
M6 Assembly Bottom:
  lines w10: -842.5,-877.33 5759.5,-877.33 ; -840.5,-1080.67 5759.5,-1080.67 ; 565.5,-1290.5 565.5,-1087.67 ; 1187.5,-877.33 1187.5,-674 ; 2027.5,-877.33 2027.5,-674 ; 3294.5,-1284 3294.5,-674 ; 4183.5,-1284 5759,-1284 5759,-674 -842.5,-674 -842.5,-1284 1754.5,-1284 5759.5,-1284 5759.5,-674
  text "COMPONENTS MARKED 'DNP' SHOULD NOT BE POPULATED." at 5552,-468 h60
  text ".VariantName" at 4508,-584 h60
  text "ASSEMBLY VARIANT:" at 5547,-584 h60
  text ".VersionControl_RevNumber" at 485.5,-806.17 h60
  text "SVN REV:" at 991.5,-806.17 h60
  text ".PCB_Rev" at 1538,-806.17 h60
  text "REV:" at 1829.5,-806.17 h60
  text ".PRJ_Number" at 2674,-806.17 h60
  text "BOARD #:" at 3219.5,-806.17 h60
  text "PCB VIEWED FROM BOTTOM SIDE" at 5696,-806.17 h60
  text ".TID" at 2674,-1009.5 h60
  text "TID #:" at 3219.5,-1009.5 h60
  text "TEXAS INSTRUMENTS" at 354.5,-1214.84 h60
  text ".Print_Time" at 1619,-1214.84 h60
  text ".Print_Date" at 2348,-1214.84 h60
  text "GENERATED    :" at 3217.5,-1214.84 h60
  text ".plot_File_Name" at 4890.5,-1214.84 h60
  text "PLOT NAME =" at 5696,-1214.84 h60
M9 Title Sheet:
  drawing of 57 lines, arcs and shapes, not listed
  text "1" at 189.84,7886.5 h70
  text "2" at 2685.5,7886.5 h70
  text "3" at 5174.84,7886.5 h70
  text "4" at 7681.51,7886.5 h70
  text "5" at 10180.5,7886.5 h70
  text "6" at 12685.5,7886.5 h70
  text "A" at -966.5,6743.5 h70
  text "A" at 13833.5,6743.5 h70
  text "B" at -966.5,4363.5 h70
  text "B" at 13833.5,4363.5 h70
  text "C" at -966.5,1988.5 h70
  text "C" at 13833.5,1988.5 h70
  text "PROJECT TITLE:" at 10793.5,127.5 h45
  text ".PRJ_Title" at 10843.5,-5.83 h70
  text "DESIGNED FOR:" at 10793.5,-173.5 h45
  text ".PRJ_Customer" at 10843.5,-313.5 h70
  text "D" at -966.5,-381.5 h70
  text "D" at 13833.5,-381.5 h70
  text "FILE NAME:" at 10793.5,-473.5 h45
  text ".PCB_File_Name_No_Path" at 10843.5,-593.5 h70
  text "Texas Instruments (TI) and/or its licensors do not warrant the accuracy or completeness of this specification" at 5824,-755.34 h45
  text "ENGINEER:" at 10793.5,-763.5 h45
  text "LAYOUT BY:" at 12298.5,-763.5 h45
  text "or any information contained therein. TI and/or its licensors do not warrant that this design will meet" at 5779.02,-868 h45
  text ".PRJ_Engineer" at 10843.5,-918.49 h70
  text ".PCB_Layout" at 12349,-918.49 h70
  text "the specifications, will be suitable for your application or fit for any particular purpose, or will operate in" at 5779.02,-980.67 h45
  text ".Layer_Name" at 27,-1008.49 h60
  text "ALTIUM DESIGNER VERSION:" at 12298.5,-1073.5 h45
  text "an implementation. TI and/or its licensors do not warrant that the design is production worthy. You should" at 5779.02,-1093.33 h45
  text "completely validate and test your design implementation to confirm the system functionality for your application." at 5824,-1206 h45
  text ".print_Scale" at 10843.5,-1206.83 h70
  text ".Application_BuildNumber" at 12349,-1206.83 h70
  text "1" at 189.84,-1413.5 h70
  text "2" at 2685.5,-1413.5 h70
  text "3" at 5174.84,-1413.5 h70
  text "4" at 7681.51,-1413.5 h70
  text "5" at 10180.5,-1413.5 h70
  text "6" at 12685.5,-1413.5 h70
M10 Fab Notes:
  drawing of 185 lines, arcs and shapes, not listed
  text "DESIGN INFORMATION" at 11831.02,5760 h60
  text "MIN. TRACK WIDTH:" at 11186.46,5580 h60
  text "10" at 12255,5580 h60
  text "MIL" at 12437.46,5580 h60
  text "7" at 12315,5455 h60
  text "MIN. CLEARANCE:" at 11186.46,5448 h60
  text "MIL" at 12437.46,5448 h60
  text "MIN. VIA PAD SIZE:" at 11186.46,5316 h60
  text "26" at 12252.71,5316 h60
  text "MIL" at 12437.46,5316 h60
  text "0.05mm (2MIL)" at 11881.46,5174.29 h60
  text "MINIMUM ANNULAR RING" at 10857.23,5170.01 h60
  text "EXTERNAL" at 12589.46,5170.01 h60
  text "PER" at 11057.23,5052 h60
  text "IPC-D-275 CLASS 2 LEVEL C" at 11277.23,5052 h60
  text "MIL, HOLES" at 12765.46,4939.71 h60
  text "+/-" at 12373,4939 h60
  text "+/-" at 13227,4939 h60
  text "REGISTRATION TOLERANCES:" at 10857.23,4934 h60
  text "METAL" at 12057,4934 h60
  text "5" at 12633.2,4934 h60
  text "3" at 13466.2,4934 h60
  text "MIL" at 13582.46,4934 h60
  text "MATERIAL:" at 10782.46,4724.54 h60
  text "FR-4 High Tg" at 11768.9,4584.21 h60
  text "FR-408" at 11203.46,4575.64 h60
  text "X" at 11615.46,4575.64 h60
  text "OTHER" at 12691.46,4575.64 h60
  text "62 MIL (1.6mm) +/-10%" at 11523.56,4412.92 h60
  text "THICKNESS:" at 10857.23,4408.64 h60
  text "X" at 11395.4,4408.64 h60
  text "OTHER" at 12808.46,4408.64 h60
  text "TOLERANCE:" at 10857.23,4250.64 h60
  text "X" at 11696.53,4250.64 h60
  text "ANSI IPC-6012 TYPE 3 CLASS 2" at 11883.48,4250.64 h60
  text "OTHER +/-" at 11883.46,4094.64 h60
  text "BOW & TWIST:" at 10857.23,3937.64 h60
  text "X" at 11696.53,3937.64 h60
  text "ANSI IPC-6012 TYPE 3 CLASS 2" at 11883.48,3937.64 h60
  text "OTHER +/-" at 11883.46,3779.13 h60
  text "DRILLING:" at 10782.46,3640.64 h60
  text "REFERENCE:" at 10857.23,3523.64 h60
  text "X" at 11505.46,3523.64 h60
  text "AS SHOWN" at 11692.46,3523.64 h60
  text "X" at 12406.46,3523.64 h60
  text "NC_DRILL FILES" at 12543.46,3523.64 h60
  text "PTH MIN COPPER THICKNESS:" at 10857.23,3365.64 h60
  text "X" at 12207.46,3365.64 h60
  text "1MIL" at 12344.46,3365.64 h60
  text "OTHER" at 12841.46,3365.64 h60
  text "BOARD FINISH:" at 10782.46,3206.64 h60
  text "SILKSCREEN:" at 10937.68,3088.64 h60
  text "X" at 11886.46,3088.64 h60
  text "TOP" at 12012.46,3088.64 h60
  text "BOTTOM" at 12523.46,3088.64 h60
  text "SILKSCREEN COLOR:" at 10937.68,2921.64 h60
  text "X" at 11885.42,2921.64 h60
  text "WHITE" at 12012.46,2921.64 h60
  text "OTHER" at 12523.46,2921.64 h60
  text "SOLDER RESIST COLOR:" at 10937.68,2751.64 h60
  text "X" at 11505.42,2592.44 h60
  text "GREEN" at 11632.46,2592.44 h60
  text "BLUE" at 12223.46,2592.44 h60
  text "OTHER" at 12761.46,2592.44 h60
  text "IMMERSION GOLD (ENIG)" at 11843.46,2403.92 h60
  text "ENEPIG" at 13181,2400.64 h60
  text "SURFACE FINISH:" at 10782.46,2399.64 h60
  text "IMM. TIN/SILVER OR EQUIV" at 11112,2242.64 h60
  text "OTHER" at 12543.46,2242.64 h60
  text "X" at 10950,2240 h60
  text "ARRAY/PANEL:" at 10782.46,2063.64 h60
  text "X" at 11650,2060 h60
  text "CUT AND TRIM PER MECH LAYER 1" at 11843.46,2059.35 h60
  text "N.C. ROUTE" at 11843.46,1907.64 h60
  text "V. SCORE" at 12709.46,1907.64 h60
  text "CERTIFICATION:" at 10782.46,1770.64 h60
  text "MATERIALS AND WORKMANSHIP FOR ALL PCBS" at 11507.46,1770.64 h60
  text "TO MEET OR EXCEED THE REQUIREMENTS OF:" at 11507.46,1672.64 h60
  text "X" at 11133.96,1536.14 h60
  text "ANSI IPC-A-600F CLASS ->" at 11272.96,1536.14 h60
  text "X" at 12912.02,1536.14 h60
  text "2" at 13030.96,1536.14 h60
  text "1" at 12715.96,1534.64 h60
  text "3" at 13384.96,1534.64 h60
  text "X" at 11136.02,1376.64 h60
  text "UL 94V-0" at 11272.96,1376.64 h60
  text "X" at 11948.02,1376.64 h60
  text "RoHS" at 12084.96,1376.64 h60
  text "OTHER" at 12729.36,1376.64 h60
  text "ADDITIONAL REQUIREMENTS:" at 10782.46,1235.64 h60
  text "MICROSECTION:" at 10857.23,1120.64 h60
  text "YES" at 11762.96,1120.64 h60
  text "REQUIRED" at 12624.46,964.5 h60
  text "BARE BOARD ELEC. TEST:" at 10857.23,961.64 h60
  text "NONE" at 12162.96,961.64 h60
  text "PER ORDER" at 13216.46,961.64 h60
  text "X" at 12035,960 h60
  text "MANUFACTURER'S UL:" at 10857.23,804.64 h60
  text "RAIL" at 12022.96,800.35 h60
  text "METAL" at 12514.77,800.35 h60
  text "X" at 12890,800 h60
  text "SILK" at 13026.46,800.35 h60
  text ".Layer_Name" at 27,-1008.49 h60
M11 Gerber Information:
  lines w10: -842,-1080.17 5758,-1080.17 ; -842,-876.83 5760,-876.83 ; -842,-673.5 -842,-1283.5 3163,-1283.5 5760,-1283.5 5760,-673.5 -841.5,-673.5 -841.5,-1283.5 734,-1283.5 ; 1623,-1283.5 1623,-673.5 ; 2890,-876.83 2890,-673.5 ; 3730,-876.83 3730,-673.5 ; 4352,-1290 4352,-1087.17
  text "ALL ARTWORK VIEWED FROM TOP SIDE" at -778.5,-805.67 h60
  text "BOARD #:" at 1698,-805.67 h60
  text ".PRJ_Number" at 2243.5,-805.67 h60
  text "REV:" at 3088,-805.67 h60
  text ".PCB_Rev" at 3379.5,-805.67 h60
  text "SVN REV:" at 3926,-805.67 h60
  text ".VersionControl_RevNumber" at 4432,-805.67 h60
  text "LAYER NAME =" at -778.5,-1008.49 h60
  text "TID #:" at 1698,-1009 h60
  text ".TID" at 2243.5,-1009 h60
  text "PLOT NAME =" at -778.5,-1214.34 h60
  text ".plot_File_Name" at 27,-1214.34 h60
  text "GENERATED    :" at 1700,-1214.34 h60
  text ".Print_Date" at 2569.5,-1214.34 h60
  text ".Print_Time" at 3298.5,-1214.34 h60
  text "TEXAS INSTRUMENTS" at 4563,-1214.34 h60
M12 Stackup:
  drawing of 305 lines, arcs and shapes, not listed
  text "Layer" at 6806.17,7415 h60
  text "Name" at 7216.09,7415 h60
  text "Material" at 8075.85,7415 h60
  text "Thickness" at 8935.62,7415 h60
  text "Constant" at 9585.46,7415 h60
  text "Board Layer Stack" at 10155.32,7415 h60
  text "Board Layer Stack" at 11275,7415 h60
  text "Board Layer Stack" at 12394.68,7415 h60
  text "1" at 6806.17,7295 h60
  text "Top Overlay" at 7216.09,7295 h60
  text "2" at 6806.17,7175 h60
  text "Top Solder" at 7216.09,7175 h60
  text "Solder Resist" at 8075.85,7175 h60
  text "0.40mil" at 8935.62,7175 h60
  text "3.5" at 9585.46,7175 h60
  text "3" at 6806.17,7055 h60
  text "Top Layer" at 7216.09,7055 h60
  text "Copper" at 8075.85,7055 h60
  text "1.40mil" at 8935.62,7055 h60
  text "4" at 6806.17,6935 h60
  text "Dielectric1" at 7216.09,6935 h60
  text "FR-4" at 8075.85,6935 h60
  text "59.20mil" at 8935.62,6935 h60
  text "4.8" at 9585.46,6935 h60
  text "5" at 6806.17,6815 h60
  text "Bottom Layer" at 7216.09,6815 h60
  text "Copper" at 8075.85,6815 h60
  text "1.40mil" at 8935.62,6815 h60
  text "6" at 6806.17,6695 h60
  text "Bottom Solder" at 7216.09,6695 h60
  text "Solder Resist" at 8075.85,6695 h60
  text "0.40mil" at 8935.62,6695 h60
  text "3.5" at 9585.46,6695 h60
  text ".Layer_Name" at 27,-1008.49 h60
M13 Component Bodies Top:
  text ".Layer_Name" at 27,-1008.49 h60
M14 Component Bodies Bottom:
  text ".Layer_Name" at 27,-1008.49 h60
M15 Courtyards Top:
  text ".Layer_Name" at 27,-1008.49 h60
M16 Courtyards Bottom:
  text ".Layer_Name" at 27,-1008.49 h60
Drill Drawing:
  circle w10: c4068.9,1789.67 r22.14
  lines w10: 4046.76,1911.43 4091.04,1911.43 4068.9,1867.15 4046.76,1911.43 ; 4046.76,1966.77 4091.04,1966.77 4091.04,2011.05 4046.76,2011.05 4046.76,1966.77 ; 4046.76,2066.4 4091.04,2066.4 4091.04,2110.67 4046.76,2110.67 4046.76,2066.4 ; 4046.76,2177.09 4057.83,2177.09 4068.9,2166.02 4079.97,2177.09 4091.04,2177.09 4079.97,2188.16 4091.04,2199.23 4079.97,2199.23 4068.9,2210.3 4057.83,2199.23 4046.76,2199.23 4057.83,2188.16 4046.76,2177.09 ; 4046.76,2309.92 4091.04,2309.92 4068.9,2265.64 4046.76,2309.92 ; 4055.62,2075.25 4082.18,2075.25 4082.18,2101.82 4055.62,2101.82 4055.62,2075.25 ; 4055.62,2181.52 4062.26,2181.52 4068.9,2174.87 4075.54,2181.52 4082.18,2181.52 4075.54,2188.16 4082.18,2194.8 4075.54,2194.8 4068.9,2201.44 4062.26,2194.8 4055.62,2194.8 4062.26,2188.16 4055.62,2181.52 ; 4055.62,2301.06 4082.18,2301.06 4068.9,2274.5 4055.62,2301.06
  lines w12: 4006,1737.64 7118.94,1737.64 ; 4006,2335.38 7118.94,2335.38 ; 4321.63,1638.02 4321.63,2435 ; 4638.82,1638.02 4638.82,2435 ; 5260.56,1638.02 5260.56,2435 ; 5504.88,1638.02 5504.88,2435 ; 5865.22,1638.02 5865.22,2435 ; 6574.73,1638.02 6574.73,2435 ; 4006,1638.02 7118.94,1638.02 7118.94,2435 4006,2435 4006,1638.02
  text "Symbol" at 4065.77,2365.26 h72
  text "Quantity" at 4351.52,2365.26 h72
  text "Finished Hole Size" at 4668.7,2365.26 h72
  text "Plated" at 5290.45,2365.26 h72
  text "Hole Type" at 5534.77,2365.26 h72
  text "Drill Layer Pair" at 5895.11,2365.26 h72
  text "Hole Tolerance" at 6604.62,2365.26 h72
  text "20" at 4351.52,2265.64 h60
  text "0.200mm (7.87mil)" at 4668.7,2265.64 h60
  text "PTH" at 5290.45,2265.64 h60
  text "Round" at 5534.77,2265.64 h60
  text "Top Layer - Bottom Layer" at 5895.11,2265.64 h60
  text "115" at 4351.52,2166.02 h60
  text "0.305mm (12.00mil)" at 4668.7,2166.02 h60
  text "PTH" at 5290.45,2166.02 h60
  text "Round" at 5534.77,2166.02 h60
  text "Top Layer - Bottom Layer" at 5895.11,2166.02 h60
  text "14" at 4351.52,2066.4 h60
  text "1.100mm (43.31mil)" at 4668.7,2066.4 h60
  text "PTH" at 5290.45,2066.4 h60
  text "Round" at 5534.77,2066.4 h60
  text "Top Layer - Bottom Layer" at 5895.11,2066.4 h60
  text "2" at 4351.52,1966.77 h60
  text "1.300mm (51.18mil)" at 4668.7,1966.77 h60
  text "PTH" at 5290.45,1966.77 h60
  text "Round" at 5534.77,1966.77 h60
  text "Top Layer - Bottom Layer" at 5895.11,1966.77 h60
  text "2" at 4351.52,1867.15 h60
  text "2.500mm (98.43mil)" at 4668.7,1867.15 h60
  text "PTH" at 5290.45,1867.15 h60
  text "Round" at 5534.77,1867.15 h60
  text "Top Layer - Bottom Layer" at 5895.11,1867.15 h60
  text "4" at 4351.52,1767.53 h60
  text "3.200mm (125.98mil)" at 4668.7,1767.53 h60
  text "PTH" at 5290.45,1767.53 h60
  text "Round" at 5534.77,1767.53 h60
  text "Top Layer - Bottom Layer" at 5895.11,1767.53 h60
  text "157 Total" at 4351.52,1667.91 h60

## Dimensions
0,0 to 3285,0 on M2 Board Dimensions
0,2450 to 0,0 on M2 Board Dimensions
